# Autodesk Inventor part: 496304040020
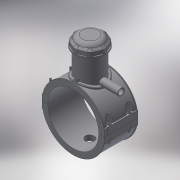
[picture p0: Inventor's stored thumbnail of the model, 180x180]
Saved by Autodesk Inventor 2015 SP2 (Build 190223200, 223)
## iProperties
Created: 2017-07
Part Number: 496304040020
Material: Generic
Description: PLASSON TAPPING SADDLE 40x20
Document SubType Name: Modeling
Designer: KIM
Mass: 121.03 g
Surface Area: 614.882 cm^2
Volume: 121.03 cm^3
Density: 1 g/cm^3
Appearance: Default
Author: KIM
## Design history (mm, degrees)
derived "496304.ipt"
feature "Solid1::496304.ipt"
feature "Solid2::496304.ipt"
feature "Solid4::496304.ipt"
feature "Solid5::496304.ipt"
tag "TaggingFeature1"
body "Solid1"
body "Solid2"
other parameters: "B_" = 66, "d_t" = 6, "H_2" = 94, "H_1" = 7, "H_" = 107, "d1" = 52, "d148" = 0.6, "d160" = 0.6, "d169" = 3.375, "d192" = 6.3, "d2" = 66, "d5" = 0, "d6" = 0.1, "d8" = 0, "d19" = 6, "d20" = 6, "d23" = 0, "d26" = 0, "d29" = 3, "d30" = 13.33333, "d31" = 6, "d32" = 0, "d33" = 0, "d34" = 0.6, "d40" = 27.04, "d41" = 36, "d43" = 0, "d45" = 0, "d47" = 86, "d70" = 15, "d72" = 0, "d73" = 6, "d75" = 5, "d76" = 0, "d77" = 2, "d79" = 15, "d82" = 5 deg, "d84" = 4, "d85" = 14, "d86" = 0, "d87" = 3, "d88" = 0, "d89" = 1, "d90" = 1, "d92" = 0, "d93" = 0.5, "d94" = 21.05263, "d96" = 53.04, "d97" = 2, "d98" = 0, "d102" = 0.4, "d120" = 140 deg, "d121" = 24.228, "d122" = 20 deg, "d123" = 104, "d124" = 31.2, "d126" = 0, "d143" = 41.2, "d145" = 9.23077, "d149" = 0.6, "d150" = 10.15385, "d154" = 0, "d156" = 26, "d157" = 160 deg, "d159" = 2.4, "d161" = 0.6, "d163" = 0, "d167" = 4, "d168" = 25.36585, "d170" = 3.375, "d172" = 0, "d173" = 1, "d176" = 20 deg, "d177" = 2.8, "d178" = 12, "d180" = 0, "d183" = 4.8, "d184" = 2.24, "d185" = 32.5, "d186" = 32.5, "d187" = 26, "d188" = 3.6, "d189" = 2.8, "d190" = 0, "d191" = 39, "d193" = 6.3, "d194" = 3.5, "d195" = 90 deg, "d197" = 0, "d199" = 0, "d200" = 6, "d202" = 0, "d203" = 94, "d204" = 34.2, "d205" = 25.2, "d206" = 30.6, "d207" = 70.5, "d208" = 73.32, "d209" = 87.42, "d210" = 30.96, "d211" = 36, "d212" = 28.8, "d213" = -2.7, "d216" = 0, "d217" = 4, "d218" = 4, "d219" = 0.8, "d224" = 0, "d230" = 2.4, "d233" = 6, "d236" = 33, "d238" = 6.02433, "d243" = 6, "d247" = 6, "d248" = 6, "d249" = 6, "d253" = 6, "d254" = 6, "d256" = 6, "d257" = 27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
